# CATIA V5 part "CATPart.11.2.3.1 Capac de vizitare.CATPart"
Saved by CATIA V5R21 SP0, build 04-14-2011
Part number: Capac de vizitare.1
Bounding box of the stored display mesh (mm): x 0 to 62, y 0 to 78.844, z -4.5 to 4
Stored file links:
  C:\Users\MIRCEA\Desktop\MOM\Mogan\model\CATPart.11.2.3.1 Capac de vizitare.CATPart
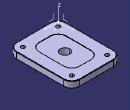
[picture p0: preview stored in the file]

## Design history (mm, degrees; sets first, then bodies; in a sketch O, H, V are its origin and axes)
Parameters
  L = 78.844 mm
  l = 62 mm
  R = 10 mm
  g = 8 mm
  h = 14 mm
  r = 10 mm
AxisSystem1: origin (0, 0, 0), X (1, 0, 0), Y (0, 1, 0), Z (0, 0, 1)
Set1
  DatumCurve1 to DatumCurve4
Body1 (main body)
  Sketch1 on xy-plane, origin (0, 0, 0), H (1, 0, 0), V (0, 1, 0)
    line L1 (10, 0) -> (52, 0)
    line L2 (62, 10) -> (62, 68.844)
    line L3 (52, 78.844) -> (10, 78.844)
    line L4 (0, 68.844) -> (0, 10)
    point P1 (62, 0)
    point P2 (0, 78.844)
    arc A1 centre (10, 10) radius 10 from (10, 0) to (0, 10) cw
    arc A2 centre (52, 10) radius 10 from (52, 0) to (62, 10) ccw
    arc A3 centre (10, 68.844) radius 10 from (0, 68.844) to (10, 78.844) cw
    arc A4 centre (52, 68.844) radius 10 from (52, 78.844) to (62, 68.844) cw
    distance O P1 = 62 {= l}
    distance P2 O = 78.844 {= L}
    radius A1 = 10 {= R}
    radius A2 = 10 {= R}
    radius A3 = 10 {= R}
    radius A4 = 10 {= R}
    horizontal: L1 H, L3 H
    vertical: L2 V, L4 V
    coincidence: L1 O, L4 O, L1 P1, L2 P1, L4 P2, L3 P2
    tangency: A1 L1, A1 L4, A2 L1, A2 L2, A3 L4, A3 L3, A4 L3, A4 L2
  Pad1: profile Sketch1, direction (0, 0, 1), length 4 {= g/2}, mirrored extent
  Sketch2 on end face of Pad1, origin (0, 0, 4), H (1, 0, 0), V (0, 1, 0)
    line L1 (24, 64.844) -> (38, 64.844)
    line L2 (48, 54.844) -> (48, 24)
    line L3 (38, 14) -> (24, 14)
    line L4 (14, 24) -> (14, 54.844)
    reference projected line E1 (0, 68.844) -> (0, 10) from edge [face of Pad1 from Sketch1.L4 | end face of Pad1]
    reference projected line E2 (52, 78.844) -> (10, 78.844) from edge [face of Pad1 from Sketch1.L3 | end face of Pad1]
    reference projected line E3 (62, 10) -> (62, 68.844) from edge [face of Pad1 from Sketch1.L2 | end face of Pad1]
    reference projected line E4 (10, 0) -> (52, 0) from edge [face of Pad1 from Sketch1.L1 | end face of Pad1]
    arc A1 centre (24, 54.844) radius 10 from (24, 64.844) to (14, 54.844) ccw
    arc A2 centre (38, 54.844) radius 10 from (48, 54.844) to (38, 64.844) ccw
    arc A3 centre (24, 24) radius 10 from (14, 24) to (24, 14) ccw
    arc A4 centre (38, 24) radius 10 from (38, 14) to (48, 24) ccw
    distance L4 E1 = 14 {= h}
    distance E2 L1 = 14 {= h}
    distance L2 E3 = 14 {= h}
    distance L3 E4 = 14 {= h}
    radius A1 = 10 {= r}
    radius A2 = 10 {= r}
    radius A3 = 10 {= r}
    radius A4 = 10 {= r}
    horizontal: L1 H, L3 H
    vertical: L2 V, L4 V
    tangency: A1 L1, A1 L4, A2 L2, A2 L1, A3 L4, A3 L3, A4 L3, A4 L2
  Pocket1: profile Sketch2, direction (0, 0, -1), length 0.5
  Mirror1: of Pocket1, Sketch2, about XY plane of AxisSystem1
  Chamfer1: length 0.5, angle 45, on edge [start face of Pad1 | face of Pad1 from Sketch1.L3]; edge [face of Pad1 from Sketch1.L3 | end face of Pad1]
  Sketch3 on start face of Pad1, origin (41, 9, -4), H (1, 0, 0), V (0, -1, 0)
    point P1 (12, 0)
    reference projected point E1 (12, 0) from Sketch7.P1
    coincidence: E1 P1
  Hole1: placed by Sketch3, at (53, 9, -4) direction (0, 0, 1), diameter 5, depth 10
  Sketch4 on start face of Pad1, origin (0, 0, -4), H (1, 0, 0), V (0, -1, 0)
    point P1 (53, -69.844)
    point P2 (9, -69.844)
    point P3 (9, -9)
    reference projected line E1 (62, -10) -> (62, -68.844) from edge [face of Chamfer1 | face of Pad1 from Sketch1.L2]
    reference projected line E2 (52, -78.844) -> (10, -78.844) from edge [face of Chamfer1 | face of Pad1 from Sketch1.L3]
    reference projected line E3 (0, -68.844) -> (0, -10) from edge [face of Chamfer1 | face of Pad1 from Sketch1.L4]
    reference projected line E4 (52, -78.844) -> (10, -78.844) from edge [face of Chamfer1 | face of Pad1 from Sketch1.L3]
    reference projected line E5 (10, 0) -> (52, 0) from edge [face of Chamfer1 | face of Pad1 from Sketch1.L1]
    reference projected line E6 (0, -68.844) -> (0, -10) from edge [face of Chamfer1 | face of Pad1 from Sketch1.L4]
    distance E1 P1 = 9
    distance P1 E2 = 9
    distance P2 E3 = 9
    distance P2 E4 = 9
    distance P3 E5 = 9
    distance P3 E6 = 9
  UserPattern1: of Hole1, copies 4, at the points of Sketch4
  Sketch5 on face of Mirror1, origin (0, 0, -3.5), H (1, 0, 0), V (0, -1, 0)
    point P1 (31, -39.422)
    circle A1 centre (31, -39.422) radius 8
    reference projected line E1 (48, -54.844) -> (48, -24) from edge of DatumCurve4
    radius A1 = 8
    distance P1 E1 = 17
  Pad2: profile Sketch5, direction (0, 0, -1), length 1
  Sketch6 on end face of Pad2, origin (0, 0, -4.5), H (1, 0, 0), V (0, -1, 0)
    circle A1 centre (31, -39.422) radius 6
    reference projected line E2 (48, -54.844) -> (48, -24) from edge of DatumCurve2
    reference projected line E3 (14, -24) -> (14, -54.844) from edge of DatumCurve3
    radius A1 = 6
    distance E2 E3 = 34 (reference)
  Pocket2: profile Sketch6, direction (0, 0, 1), through (limit type 6)
  Sketch7 on start face of Pad1, origin (0, 0, -4), H (1, 0, 0), V (0, -1, 0)
    point P1 (53, -9)
    reference projected line E1 (10, 0) -> (52, 0) from edge [face of Chamfer1 | face of Pad1 from Sketch1.L1]
    reference projected line E2 (62, -10) -> (62, -68.844) from edge [face of Chamfer1 | face of Pad1 from Sketch1.L2]
    distance P1 E1 = 9
    distance P1 E2 = 9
